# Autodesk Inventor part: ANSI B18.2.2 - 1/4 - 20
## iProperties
Comments: To add or edit properties for Autodesk Inventor files, use iProperties.
Created: 2004-12
Part Number: ANSI B18.2.2 - 1/4 - 20
Vendor: Autodesk Inc.
Document SubType Name: Modeling
Designer: John Blackburn
Material: Default
Description: Hex Nut
Standard: ANSI B18.2.2
Alert: To add or edit properties for Autodesk Inventor files, use iProperties.
Control State: 0
Master: False
Checked Out: False
Shininess: 64.0
Length Units: 11272
Angle Units: 11279
Time Units: 11290
Mass Units: 11286
Length Display Precision: 3
Angle Display Precision: 2
Compacted: True
EGR: 3
Classification: un/spsc 31161727
Density: 0.0
Volumn: 0.0
Area: 0.0
PropertySet Name: Model Information
Author: John Blackburn
Revision Number: 8
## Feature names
1. Body [Extrusion]
2. Chamfer1 [Revolution]
3. Thread [Hole]
4. Chamfer2
5. Chamfer3
